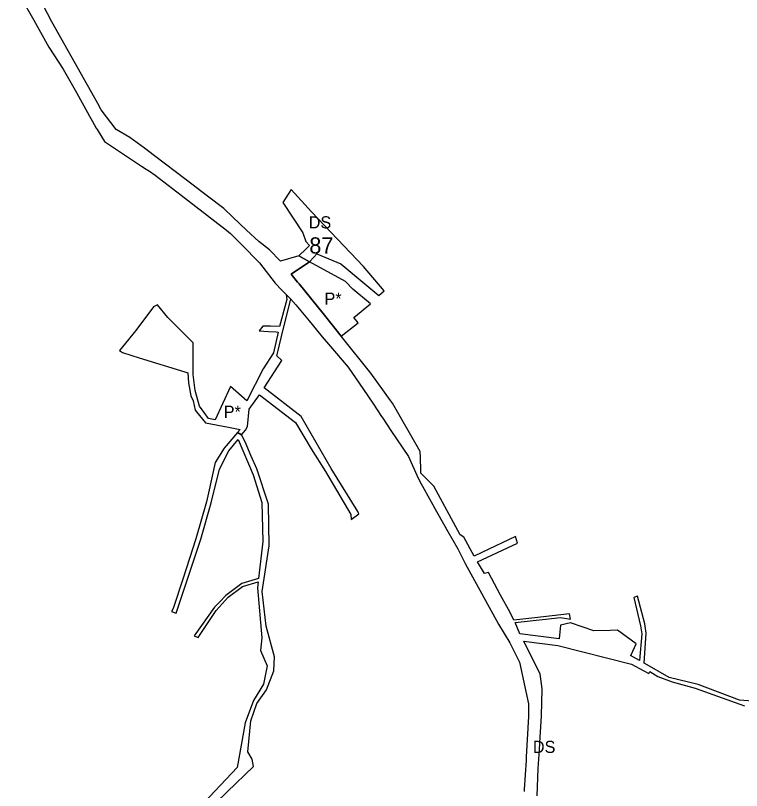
# Model space of a CAD drawing. Extents: x -477304 to -465641, y -1159113 to -1149285.
# Drawn here: x -474479 to -473942, y -1155620 to -1155046 of the extents above; entities that cross this region are included whole.
import ezdxf

# ---------------------------------------------------------------- set-up
doc = ezdxf.new("R2010")
doc.units = 0
for name, color, linetype in [('14', 7, 'Continuous'), ('34', 7, 'Continuous'), ('35', 7, 'Continuous'), ('60', 7, 'Continuous')]:
    doc.layers.add(name, color=color, linetype=linetype)

msp = doc.modelspace()

# ---------------------------------------------------------------- linework, layer by layer
at = {"layer": '14'}
for p, q in [((-474275, -1155175.09), (-474281.1, -1155184.91)), ((-474259.89, -1155191.65), (-474275, -1155175.09)), ((-474221.38, -1155232.34), (-474259.89, -1155191.65)), ((-474264.2, -1155213.61), (-474261.42, -1155216.73)), ((-474261.42, -1155216.73), (-474263.85, -1155219.06)), ((-474263.85, -1155219.06), (-474269.37, -1155224.37)), ((-474258.26, -1155225.37), (-474255.92, -1155222.91)), ((-474255.92, -1155222.91), (-474238.13, -1155230.32)), ((-474269.37, -1155224.37), (-474261.46, -1155228.73)), ((-474261.46, -1155228.73), (-474258.26, -1155225.37)), ((-474206.22, -1155250.33), (-474221.38, -1155232.34))]:
    msp.add_line(p, q, dxfattribs=at)
for points in [[(-474281.1, -1155184.91), (-474266.3, -1155207.27), (-474264.2, -1155213.61)], [(-474238.13, -1155230.32), (-474210.11, -1155253.66), (-474206.22, -1155250.33)]]:
    msp.add_lwpolyline(points, dxfattribs=at)
at = {"layer": '34'}
for p, q in [((-474261.46, -1155228.73), (-474275.05, -1155237.94)), ((-474234.87, -1155243.39), (-474261.46, -1155228.73)), ((-474275.05, -1155237.94), (-474270.23, -1155243.88)), ((-474270.23, -1155243.88), (-474269.19, -1155244.98)), ((-474269.19, -1155244.98), (-474251.3, -1155267.01)), ((-474278.11, -1155256.77), (-474283.69, -1155276.72)), ((-474281.32, -1155280.87), (-474275.26, -1155256.47)), ((-474275.26, -1155256.47), (-474278.71, -1155252.9)), ((-474278.71, -1155252.9), (-474278.11, -1155256.77)), ((-474373.87, -1155260.58), (-474376.81, -1155262.03)), ((-474366.21, -1155270.09), (-474373.87, -1155260.58)), ((-474228.62, -1155269.87), (-474216.17, -1155259.91)), ((-474251.3, -1155267.01), (-474237.88, -1155283.77)), ((-474296.05, -1155276.35), (-474298.6, -1155279.91)), ((-474298.6, -1155279.91), (-474291.91, -1155280.3)), ((-474290.38, -1155276.52), (-474296.05, -1155276.35)), ((-474291.91, -1155280.3), (-474286.09, -1155280.64)), ((-474283.69, -1155276.72), (-474290.38, -1155276.52)), ((-474284.58, -1155280.73), (-474288, -1155296.06)), ((-474286.09, -1155280.64), (-474284.58, -1155280.73)), ((-474395.5, -1155286.28), (-474402.18, -1155294.39)), ((-474391.19, -1155281.05), (-474395.5, -1155286.28)), ((-474284.7, -1155294.48), (-474281.32, -1155280.87)), ((-474402.18, -1155294.39), (-474399.99, -1155295.96)), ((-474288, -1155296.06), (-474295.63, -1155308.01)), ((-474295.01, -1155322.18), (-474282.02, -1155301.8)), ((-474295.63, -1155308.01), (-474307.86, -1155331.63)), ((-474351.45, -1155310.92), (-474350.96, -1155318.45)), ((-474346.09, -1155323.97), (-474347.56, -1155312.12)), ((-474350.96, -1155318.45), (-474349.37, -1155327.88)), ((-474342.9, -1155335.58), (-474346.09, -1155323.97)), ((-474319.89, -1155321.15), (-474331.37, -1155345.75)), ((-474307.86, -1155331.63), (-474319.89, -1155321.15)), ((-474267.57, -1155343.31), (-474295.01, -1155322.18)), ((-474349.37, -1155327.88), (-474347.68, -1155331.82)), ((-474347.68, -1155331.82), (-474346.1, -1155338.56)), ((-474339.42, -1155340.38), (-474342.9, -1155335.58)), ((-474346.1, -1155338.56), (-474345.2, -1155339.8)), ((-474336.25, -1155344.75), (-474339.42, -1155340.38)), ((-474245.46, -1155381.83), (-474267.57, -1155343.31)), ((-474331.37, -1155345.75), (-474336.25, -1155344.75)), ((-474271.73, -1155347.69), (-474260.1, -1155367.23)), ((-474321.5, -1155351.27), (-474312.88, -1155352.91)), ((-474312.88, -1155352.91), (-474314.74, -1155355.08)), ((-474314.74, -1155355.08), (-474311.67, -1155356.98)), ((-474311.67, -1155356.98), (-474308.92, -1155353.4)), ((-474308.92, -1155353.4), (-474307.45, -1155350.74)), ((-474311.67, -1155356.98), (-474311.67, -1155356.98)), ((-474260.1, -1155367.23), (-474249.67, -1155384.13)), ((-474249.67, -1155384.13), (-474230.81, -1155415.82)), ((-474230.81, -1155415.82), (-474230.55, -1155419.6)), ((-474230.55, -1155419.6), (-474224.83, -1155415.28))]:
    msp.add_line(p, q, dxfattribs=at)
for points in [[(-474216.17, -1155259.91), (-474229.33, -1155249), (-474234.87, -1155243.39)], [(-474376.81, -1155262.03), (-474390.04, -1155279.53), (-474391.19, -1155281.05)], [(-474347.56, -1155312.12), (-474347.64, -1155288.78), (-474366.21, -1155270.09)], [(-474237.88, -1155283.77), (-474225.5, -1155273.84), (-474228.62, -1155269.87)], [(-474399.99, -1155295.96), (-474387.54, -1155299.8), (-474353.64, -1155310.24), (-474351.45, -1155310.92)], [(-474282.02, -1155301.8), (-474285.65, -1155298.3), (-474284.7, -1155294.48)], [(-474307.45, -1155350.74), (-474306.01, -1155337.89), (-474298.48, -1155327.15), (-474271.73, -1155347.69)], [(-474345.2, -1155339.8), (-474338.46, -1155348.11), (-474321.5, -1155351.27)], [(-474224.83, -1155415.28), (-474225.77, -1155413.75), (-474245.46, -1155381.83)]]:
    msp.add_lwpolyline(points, dxfattribs=at)
at = {"layer": '35'}
for p, q in [((-474452.27, -1155051.03), (-474473.97, -1155008.34)), ((-474479.1, -1155025.98), (-474465.55, -1155049.89)), ((-474465.55, -1155049.89), (-474454.49, -1155069.69)), ((-474454.49, -1155069.69), (-474443.89, -1155086.15)), ((-474443.89, -1155086.15), (-474435.03, -1155101.76)), ((-474435.03, -1155101.76), (-474428.61, -1155113.23)), ((-474428.61, -1155113.23), (-474424.29, -1155120.81)), ((-474415.67, -1155116.17), (-474418.25, -1155111.57)), ((-474411.68, -1155121.4), (-474415.67, -1155116.17)), ((-474424.29, -1155120.81), (-474422.25, -1155124.4)), ((-474422.25, -1155124.4), (-474419.28, -1155129.82)), ((-474408.5, -1155125.57), (-474411.68, -1155121.4)), ((-474404.62, -1155130.66), (-474408.5, -1155125.57)), ((-474419.28, -1155129.82), (-474419.28, -1155129.82)), ((-474419.28, -1155129.82), (-474418.71, -1155130.77)), ((-474418.71, -1155130.77), (-474413.33, -1155139.72)), ((-474394.36, -1155136.72), (-474404.62, -1155130.66)), ((-474383.69, -1155144.63), (-474394.36, -1155136.72)), ((-474376.13, -1155150.24), (-474383.69, -1155144.63)), ((-474352.82, -1155168.06), (-474376.13, -1155150.24)), ((-474379.91, -1155161.73), (-474375.73, -1155164.51)), ((-474375.73, -1155164.51), (-474356.45, -1155179.35)), ((-474337.02, -1155180.16), (-474352.82, -1155168.06)), ((-474356.45, -1155179.35), (-474345.63, -1155187.72)), ((-474324.96, -1155189.35), (-474337.02, -1155180.16)), ((-474345.63, -1155187.72), (-474322.8, -1155205.4)), ((-474318.27, -1155195.67), (-474324.96, -1155189.35)), ((-474308.09, -1155205.29), (-474318.27, -1155195.67)), ((-474322.8, -1155205.4), (-474319.82, -1155207.9)), ((-474299.06, -1155213.82), (-474308.09, -1155205.29)), ((-474319.82, -1155207.9), (-474317.72, -1155210.02)), ((-474317.72, -1155210.02), (-474311.9, -1155215.92)), ((-474269.37, -1155224.37), (-474282.84, -1155228.34)), ((-474275.05, -1155237.94), (-474261.46, -1155228.73)), ((-474261.46, -1155228.73), (-474269.37, -1155224.37)), ((-474270.23, -1155243.88), (-474275.05, -1155237.94)), ((-474286.81, -1155244.52), (-474281.87, -1155249.63)), ((-474269.19, -1155244.98), (-474270.23, -1155243.88)), ((-474251.3, -1155267.01), (-474269.19, -1155244.98)), ((-474281.87, -1155249.63), (-474278.71, -1155252.9)), ((-474278.71, -1155252.9), (-474275.26, -1155256.47)), ((-474275.26, -1155256.47), (-474271.59, -1155260.58)), ((-474271.59, -1155260.58), (-474261.68, -1155272.54)), ((-474237.88, -1155283.77), (-474251.3, -1155267.01)), ((-474261.68, -1155272.54), (-474256.15, -1155279.21)), ((-474256.15, -1155279.21), (-474252.02, -1155284.28)), ((-474252.02, -1155284.28), (-474245.79, -1155291.57)), ((-474215.95, -1155311.16), (-474237.88, -1155283.77)), ((-474245.79, -1155291.57), (-474232.82, -1155306.74)), ((-474232.82, -1155306.74), (-474221.51, -1155323.26)), ((-474221.51, -1155323.26), (-474214.53, -1155333.45)), ((-474214.53, -1155333.45), (-474208.1, -1155343.22)), ((-474179.48, -1155369.12), (-474199.96, -1155333.5)), ((-474208.1, -1155343.22), (-474207.16, -1155344.64)), ((-474207.16, -1155344.64), (-474201.13, -1155353.55)), ((-474314.74, -1155355.08), (-474324.72, -1155366.77)), ((-474311.67, -1155356.98), (-474314.74, -1155355.08)), ((-474201.13, -1155353.55), (-474196.93, -1155359.89)), ((-474321.24, -1155368.73), (-474314.3, -1155360.4)), ((-474314.3, -1155360.4), (-474303.22, -1155386.54)), ((-474309.18, -1155362.13), (-474311.67, -1155356.98)), ((-474311.67, -1155356.98), (-474311.67, -1155356.98)), ((-474196.93, -1155359.89), (-474188.2, -1155373.04)), ((-474324.72, -1155366.77), (-474331.18, -1155377.25)), ((-474304.54, -1155372.56), (-474309.18, -1155362.13)), ((-474179.36, -1155373.45), (-474179.48, -1155369.12)), ((-474331.18, -1155377.25), (-474336.21, -1155399.92)), ((-474188.2, -1155373.04), (-474181.04, -1155388.94)), ((-474179.07, -1155383.49), (-474179.36, -1155373.45)), ((-474179.02, -1155385.26), (-474179.07, -1155383.49)), ((-474181.04, -1155388.94), (-474178.73, -1155393.14)), ((-474177.09, -1155387.18), (-474179.02, -1155385.26)), ((-474169.33, -1155394.87), (-474177.09, -1155387.18)), ((-474178.73, -1155393.14), (-474177.75, -1155394.89)), ((-474177.75, -1155394.89), (-474167.3, -1155413.75)), ((-474149.84, -1155431.01), (-474169.33, -1155394.87)), ((-474336.21, -1155399.92), (-474337.69, -1155406.61)), ((-474337.69, -1155406.61), (-474345.64, -1155433.88)), ((-474341.86, -1155434.19), (-474334.18, -1155407.21)), ((-474167.3, -1155413.75), (-474162.28, -1155422.81)), ((-474162.28, -1155422.81), (-474158.99, -1155428.49)), ((-474158.99, -1155428.49), (-474151.52, -1155441.36)), ((-474360.03, -1155488.94), (-474341.86, -1155434.19)), ((-474345.64, -1155433.88), (-474354.86, -1155463.07)), ((-474147.15, -1155432.58), (-474149.84, -1155431.01)), ((-474139.57, -1155446.75), (-474147.15, -1155432.58)), ((-474107.51, -1155437.03), (-474108.94, -1155432.21)), ((-474295.99, -1155435.78), (-474299.12, -1155463.35)), ((-474151.52, -1155441.36), (-474151.09, -1155442.16)), ((-474137.06, -1155451.04), (-474107.51, -1155437.03)), ((-474151.09, -1155442.16), (-474146.09, -1155452.04)), ((-474146.09, -1155452.04), (-474121.57, -1155497.2)), ((-474131.97, -1155459.65), (-474137.06, -1155451.04)), ((-474354.86, -1155463.07), (-474362.29, -1155485.51)), ((-474129.01, -1155458.77), (-474131.97, -1155459.65)), ((-474120.08, -1155475.58), (-474129.01, -1155458.77)), ((-474321.63, -1155477.13), (-474311.01, -1155469.09)), ((-474311.01, -1155469.09), (-474299.38, -1155465.62)), ((-474296.38, -1155472.9), (-474295.53, -1155466.42)), ((-474293.5, -1155498.56), (-474296.38, -1155472.9)), ((-474112.98, -1155488.36), (-474120.08, -1155475.58)), ((-474330.6, -1155487.08), (-474321.63, -1155477.13)), ((-474343.98, -1155507), (-474330.6, -1155487.08)), ((-474109.1, -1155495.92), (-474075.52, -1155492.14)), ((-474068.89, -1155489.46), (-474094.63, -1155492.35)), ((-474075.52, -1155492.14), (-474068.28, -1155493.49)), ((-474068.28, -1155493.49), (-474068.89, -1155489.46)), ((-474121.57, -1155497.2), (-474113.04, -1155510.85)), ((-474105.67, -1155504.18), (-474109.1, -1155495.92)), ((-474075.62, -1155497.74), (-474076.68, -1155508.03)), ((-474016.31, -1155498.35), (-474015.28, -1155504.31)), ((-474076.68, -1155508.03), (-474105.67, -1155504.18)), ((-474038.75, -1155501.86), (-474050.8, -1155501.9)), ((-474033.51, -1155501.59), (-474038.75, -1155501.86)), ((-474019.51, -1155511.57), (-474033.51, -1155501.59)), ((-474015.28, -1155504.31), (-474017.08, -1155524.02)), ((-474013.76, -1155525.92), (-474012.11, -1155503.75)), ((-474346.77, -1155505.76), (-474343.98, -1155507)), ((-474090.63, -1155533.99), (-474102.75, -1155509.76)), ((-474102.75, -1155509.76), (-474077.66, -1155512.77)), ((-474113.04, -1155510.85), (-474106, -1155525.26)), ((-474077.66, -1155512.77), (-474023, -1155526.75)), ((-474017.08, -1155524.02), (-474023.66, -1155520.25)), ((-474106, -1155525.26), (-474099.18, -1155556.08)), ((-474023, -1155526.75), (-474013.95, -1155531.67)), ((-474013.16, -1155526.26), (-474013.76, -1155525.92)), ((-473995.16, -1155536.54), (-474013.16, -1155526.26)), ((-474292.89, -1155527.89), (-474295.45, -1155541.42)), ((-474013.95, -1155531.67), (-474010.3, -1155533.65)), ((-474010.3, -1155533.65), (-474009.51, -1155532.19)), ((-474009.51, -1155532.19), (-474003.59, -1155535.82)), ((-474090.11, -1155537.68), (-474090.63, -1155533.99)), ((-474089.09, -1155544.94), (-474090.11, -1155537.68)), ((-474003.59, -1155535.82), (-473992.92, -1155539.75)), ((-473992.92, -1155539.75), (-473976.02, -1155544.52)), ((-473976.02, -1155544.52), (-473939.42, -1155557.53)), ((-474089.57, -1155564.92), (-474089.09, -1155544.94)), ((-474099.18, -1155556.08), (-474099.34, -1155565.54)), ((-474092.13, -1155603.85), (-474091.25, -1155590.25)), ((-474101.07, -1155597.74), (-474102.42, -1155619.45)), ((-474315.02, -1155603.21), (-474358.63, -1155649.3)), ((-474092.93, -1155624.24), (-474092.13, -1155603.85)), ((-474102.42, -1155619.45), (-474102.52, -1155621.05))]:
    msp.add_line(p, q, dxfattribs=at)
for points in [[(-474418.25, -1155111.57), (-474425.86, -1155098.03), (-474452.27, -1155051.03)], [(-474413.33, -1155139.72), (-474385.78, -1155157.84), (-474382.29, -1155160.15), (-474379.91, -1155161.73)], [(-474311.9, -1155215.92), (-474298.45, -1155229.53), (-474286.81, -1155244.52)], [(-474282.84, -1155228.34), (-474291.03, -1155219.9), (-474299.06, -1155213.82)], [(-474199.96, -1155333.5), (-474201.36, -1155331.54), (-474215.95, -1155311.16)], [(-474334.18, -1155407.21), (-474328.06, -1155382.2), (-474321.24, -1155368.73)], [(-474295.53, -1155466.42), (-474291.21, -1155439.01), (-474291.79, -1155408.17), (-474300.53, -1155381.97), (-474304.54, -1155372.56)], [(-474303.22, -1155386.54), (-474296.71, -1155406.95), (-474295.99, -1155435.78)], [(-474108.94, -1155432.21), (-474133.78, -1155444), (-474139.57, -1155446.75)], [(-474299.12, -1155463.35), (-474311.6, -1155466.89), (-474323.31, -1155475.96), (-474328.06, -1155480.81), (-474331.65, -1155484.54), (-474346.77, -1155505.76)], [(-474299.38, -1155465.62), (-474299.9, -1155470.25), (-474296.68, -1155507.23), (-474297.62, -1155516.59), (-474292.89, -1155527.89)], [(-474012.11, -1155503.75), (-474013.28, -1155496.79), (-474018.49, -1155476.25), (-474021.23, -1155477.42), (-474016.31, -1155498.35)], [(-474362.29, -1155485.51), (-474363.64, -1155487.58), (-474360.03, -1155488.94)], [(-474094.63, -1155492.35), (-474110.04, -1155494.08), (-474112.98, -1155488.36)], [(-474287.87, -1155531.73), (-474287.26, -1155521.3), (-474293.5, -1155498.56)], [(-474050.8, -1155501.9), (-474068.18, -1155496.19), (-474075.62, -1155497.74)], [(-474023.66, -1155520.25), (-474023.39, -1155519.88), (-474019.51, -1155511.57)], [(-474300.52, -1155555.74), (-474293.27, -1155545.65), (-474287.87, -1155531.73)], [(-473891.47, -1155554.36), (-473917.77, -1155555.45), (-473943.17, -1155553.33), (-473973.8, -1155541.7), (-473995.16, -1155536.54)], [(-474295.45, -1155541.42), (-474302.8, -1155553.51), (-474309.02, -1155570.06), (-474315.02, -1155603.21)], [(-474306.99, -1155591.51), (-474304.9, -1155568.75), (-474300.52, -1155555.74)], [(-474099.34, -1155565.54), (-474100.93, -1155595.43), (-474101.07, -1155597.74)], [(-474091.25, -1155590.25), (-474090.9, -1155584.92), (-474089.57, -1155564.92)], [(-474355.15, -1155653.13), (-474322.44, -1155621.35), (-474302.84, -1155602.37), (-474303.86, -1155597.03), (-474306.99, -1155591.51)]]:
    msp.add_lwpolyline(points, dxfattribs=at)

# ---------------------------------------------------------------- texts
at = {"layer": '14'}
msp.add_text('DS', height=9, dxfattribs=at).set_placement((-474262.05, -1155204.02))
at = {"layer": '34'}
for p in [(-474250.35, -1155260.54), (-474324.95, -1155344.3)]:
    msp.add_text('P*', height=9, dxfattribs=at).set_placement(p)
at = {"layer": '35'}
msp.add_text('DS', height=9, dxfattribs=at).set_placement((-474096.08, -1155592.45))
at = {"layer": '60'}
msp.add_text('87', height=12, dxfattribs=at).set_placement((-474261.58, -1155222.65))

doc.saveas('drawing.dxf')
